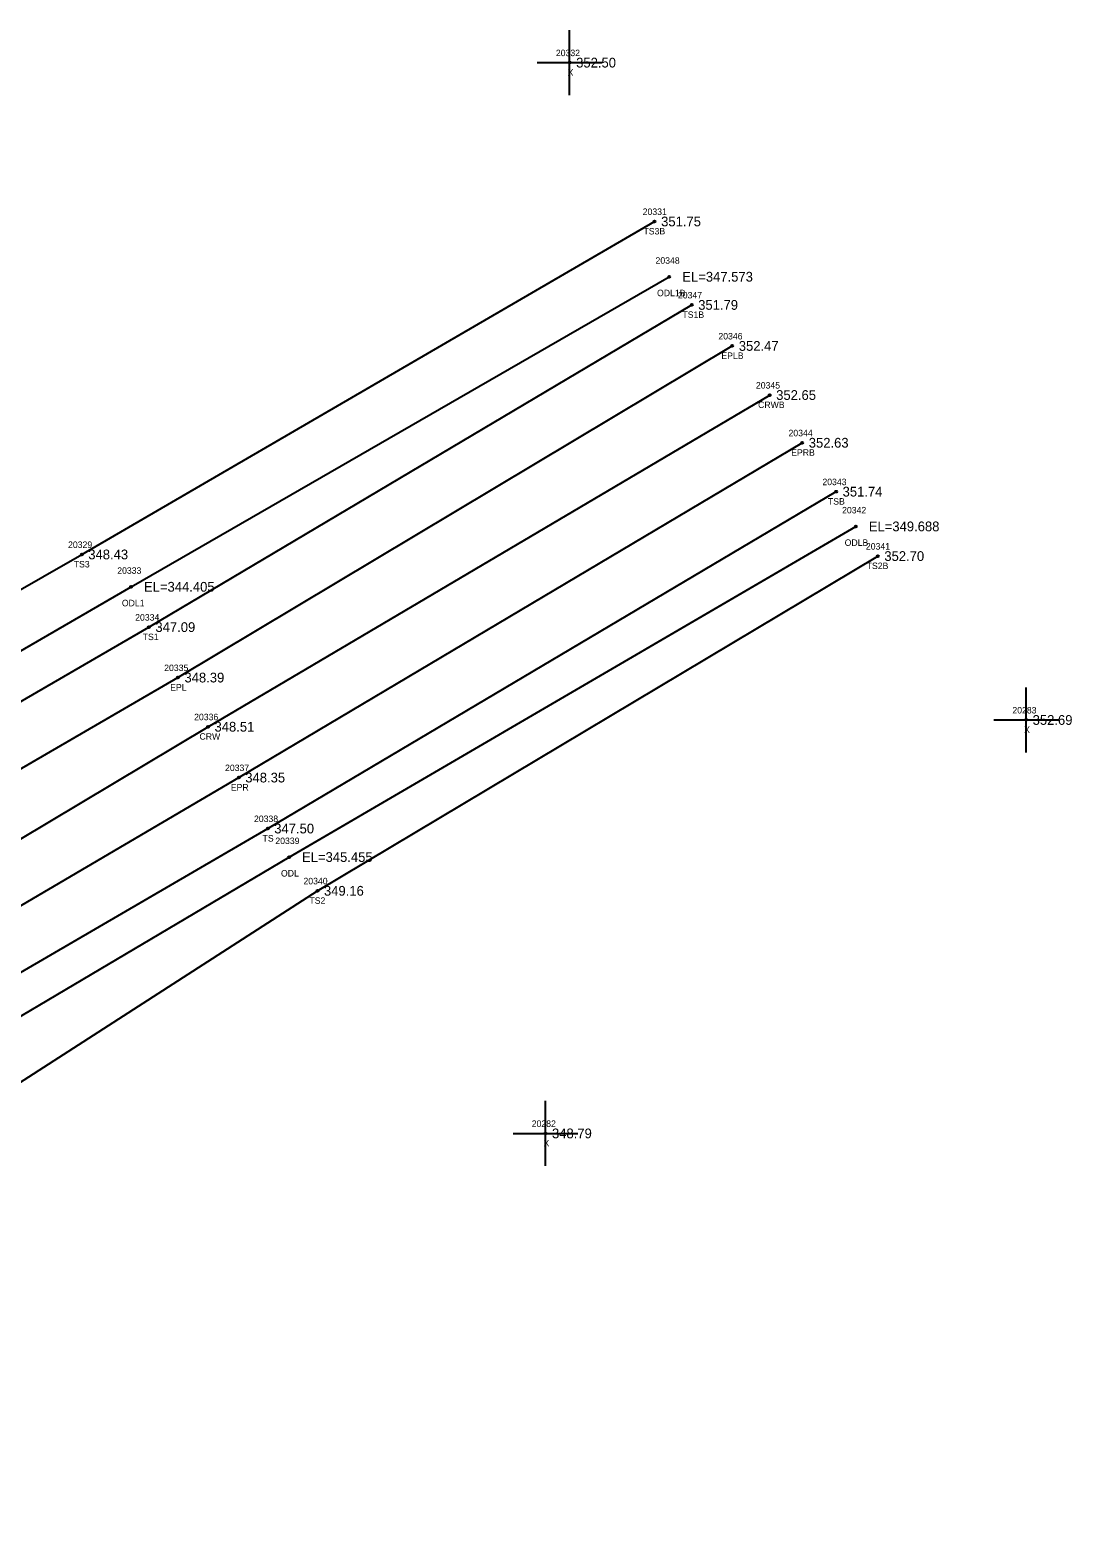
# Model space of a CAD drawing. Extents: x 2231109 to 2232328, y 1035718 to 1036919.
# Drawn here: x 2232167.8 to 2232328.2, y 1036686.7 to 1036918.9 of the extents above; entities that cross this region are included whole.
import ezdxf

# ---------------------------------------------------------------- set-up
doc = ezdxf.new("R2010")
doc.units = 0
for name, color, linetype in [('RD_DTM_BkLn1', 7, 'Continuous'), ('RD_DTM_BkLn2', 7, 'Continuous'), ('RD_DTM_BkLn_txCode', 7, 'Continuous'), ('RD_EX_H2O', 7, 'Continuous'), ('RD_EX_H2O_txCode', 7, 'Continuous'), ('RD_EX_Misc', 7, 'Continuous'), ('RD_EX_Misc_txCode', 7, 'Continuous'), ('RD_EX_Road', 7, 'Continuous'), ('RD_EX_Road_txCode', 7, 'Continuous'), ('RD_EX_TX_H2O_ELEV', 7, 'Continuous'), ('RD_EX_TX_Misc_ELEV', 7, 'Continuous'), ('RD_EX_TX_Road_ELEV', 7, 'Continuous'), ('RD_HC_Survey_ELEV', 7, 'Continuous'), ('RD_HC_Survey_txCode', 7, 'Continuous'), ('RD_SMD_Locator', 7, 'Continuous')]:
    doc.layers.add(name, color=color, linetype=linetype)

msp = doc.modelspace()

# ---------------------------------------------------------------- linework, layer by layer
at = {"layer": 'RD_DTM_BkLn1'}
msp.add_lwpolyline([(2231606.1, 1036462.92), (2231686.87, 1036511.89), (2231772.7, 1036562.84), (2231856.39, 1036612), (2231941.22, 1036662.52), (2232026.21, 1036712.41), (2232112.3, 1036762.07), (2232195.17, 1036811.63), (2232281.68, 1036862.71)], dxfattribs=at)
at = {"layer": 'RD_DTM_BkLn2'}
for points in [[(2231735.08, 1036566.99), (2231733.44, 1036571.38), (2231838.97, 1036638.65), (2231923.32, 1036688.26), (2232007.46, 1036737.64), (2232093.05, 1036790.84), (2232175.73, 1036838.16), (2232263.96, 1036889.44)], [(2231735.08, 1036566.99), (2231739.37, 1036565.02), (2231846.03, 1036627.82), (2231929.8, 1036677.63), (2232016.53, 1036728.58), (2232102.07, 1036778.24), (2232186.07, 1036826.97), (2232269.67, 1036876.59)], [(2231718.4, 1036498.96), (2231713.38, 1036506.48), (2231734.88, 1036516.5), (2231783.19, 1036543.78), (2231867.56, 1036594.75), (2232035.39, 1036697.6), (2232204.37, 1036795.95), (2232291.91, 1036847.83)], [(2231718.4, 1036498.96), (2231722.77, 1036493.83), (2231728.85, 1036494.16), (2231749.87, 1036507.43), (2231788.02, 1036534.9), (2231874.52, 1036587.15), (2231959.93, 1036637.18), (2232042.1, 1036685.84), (2232133.02, 1036735.49), (2232212.03, 1036786.36), (2232298.34, 1036837.91)]]:
    msp.add_lwpolyline(points, dxfattribs=at)
at = {"layer": 'RD_EX_H2O'}
for points in [[(2231741.7, 1036569.83), (2231843.08, 1036632.45), (2231926.34, 1036681.31), (2232011.09, 1036733.11), (2232099.56, 1036784.62), (2232183.31, 1036833.18), (2232266.22, 1036880.93)], [(2231720.77, 1036499.78), (2231736.43, 1036508.96), (2231742.17, 1036508.27), (2231745.29, 1036514.03), (2231785.52, 1036539.9), (2231869.59, 1036591.16), (2232038.46, 1036693), (2232129.43, 1036745.26), (2232207.65, 1036791.56), (2232294.95, 1036842.48)]]:
    msp.add_lwpolyline(points, dxfattribs=at)
at = {"layer": 'RD_EX_Misc'}
for p, q in [((2232250.87, 1036908.9), (2232250.87, 1036918.9)), ((2232245.87, 1036913.9), (2232255.87, 1036913.9)), ((2232321.18, 1036807.67), (2232321.18, 1036817.67)), ((2232316.18, 1036812.67), (2232326.18, 1036812.67)), ((2232247.15, 1036744), (2232247.15, 1036754)), ((2232242.15, 1036749), (2232252.15, 1036749))]:
    msp.add_line(p, q, dxfattribs=at)
at = {"layer": 'RD_EX_Road'}
for points in [[(2231606.1, 1036462.92), (2231601.27, 1036470.82), (2231681.58, 1036519.84), (2231764.99, 1036568.78), (2231851.5, 1036619.95), (2231935.62, 1036669.65), (2232021.78, 1036720.22), (2232106.75, 1036770.57), (2232190.54, 1036819.2), (2232275.92, 1036870.27)], [(2231606.1, 1036462.92), (2231610.57, 1036455.36), (2231692.09, 1036503.24), (2231706.07, 1036512.59), (2231777.1, 1036553.27), (2231861.39, 1036604.65), (2231946.39, 1036654.77), (2232031.07, 1036704.2), (2232117.06, 1036755.16), (2232199.91, 1036803.8), (2232286.7, 1036855.36)]]:
    msp.add_lwpolyline(points, dxfattribs=at)
at = {"layer": 'RD_SMD_Locator'}
for centre in [(2232250.87, 1036913.9), (2232263.96, 1036889.44), (2232266.22, 1036880.93), (2232269.67, 1036876.59), (2232275.92, 1036870.27), (2232281.68, 1036862.71), (2232286.7, 1036855.36), (2232291.91, 1036847.83), (2232294.95, 1036842.48), (2232175.73, 1036838.16), (2232298.34, 1036837.91), (2232183.31, 1036833.18), (2232186.07, 1036826.97), (2232190.54, 1036819.2), (2232195.17, 1036811.63), (2232321.18, 1036812.67), (2232199.91, 1036803.8), (2232204.37, 1036795.95), (2232207.65, 1036791.56), (2232212.03, 1036786.36), (2232247.15, 1036749)]:
    msp.add_circle(centre, 0.15, dxfattribs=at)

# ---------------------------------------------------------------- texts
at = {"layer": 'RD_DTM_BkLn_txCode'}
for s, p in [('20331', (2232262.12, 1036890.44)), ('TS3B', (2232262.24, 1036887.44)), ('20347', (2232267.55, 1036877.59)), ('TS1B', (2232268.24, 1036874.59)), ('20343', (2232289.8, 1036848.83)), ('TSB', (2232290.65, 1036845.83)), ('20329', (2232173.61, 1036839.16)), ('20341', (2232296.5, 1036838.91)), ('TS3', (2232174.49, 1036836.16)), ('TS2B', (2232296.62, 1036835.91)), ('20334', (2232183.95, 1036827.97)), ('TS1', (2232185.11, 1036824.97)), ('20338', (2232202.25, 1036796.95)), ('TS', (2232203.57, 1036793.95)), ('20340', (2232209.87, 1036787.36)), ('TS2', (2232210.79, 1036784.36))]:
    msp.add_text(s, height=1, dxfattribs=at).set_placement(p)
at = {"layer": 'RD_EX_H2O_txCode'}
for s, p in [('20348', (2232264.1, 1036882.93)), ('ODL1B', (2232264.33, 1036877.93)), ('20342', (2232292.83, 1036844.48)), ('ODLB', (2232293.23, 1036839.48)), ('20333', (2232181.19, 1036835.18)), ('ODL1', (2232181.9, 1036830.18)), ('20339', (2232205.54, 1036793.56)), ('ODL', (2232206.41, 1036788.56))]:
    msp.add_text(s, height=1, dxfattribs=at).set_placement(p)
at = {"layer": 'RD_EX_Misc_txCode'}
for s, p in [('20332', (2232248.75, 1036914.9)), ('X', (2232250.55, 1036911.9)), ('20283', (2232319.06, 1036813.67)), ('X', (2232320.87, 1036810.67)), ('20282', (2232245.03, 1036750)), ('X', (2232246.84, 1036747))]:
    msp.add_text(s, height=1, dxfattribs=at).set_placement(p)
at = {"layer": 'RD_EX_Road_txCode'}
for s, p in [('20346', (2232273.78, 1036871.27)), ('EPLB', (2232274.24, 1036868.27)), ('20344', (2232284.58, 1036856.36)), ('EPRB', (2232284.99, 1036853.36)), ('20335', (2232188.42, 1036820.2)), ('EPL', (2232189.34, 1036817.2)), ('20337', (2232197.79, 1036804.8)), ('EPR', (2232198.68, 1036801.8))]:
    msp.add_text(s, height=1, dxfattribs=at).set_placement(p)
at = {"layer": 'RD_EX_TX_H2O_ELEV'}
for s, p in [('EL=347.573', (2232268.22, 1036880.18)), ('EL=349.688', (2232296.95, 1036841.73)), ('EL=344.405', (2232185.31, 1036832.43)), ('EL=345.455', (2232209.65, 1036790.81))]:
    msp.add_text(s, height=1.5, dxfattribs=at).set_placement(p)
at = {"layer": 'RD_EX_TX_Misc_ELEV'}
for s, p in [('352.50', (2232251.87, 1036913.15)), ('351.75', (2232264.96, 1036888.69)), ('351.79', (2232270.67, 1036875.84)), ('351.74', (2232292.91, 1036847.08)), ('348.43', (2232176.73, 1036837.41)), ('352.70', (2232299.34, 1036837.16)), ('347.09', (2232187.07, 1036826.22)), ('352.69', (2232322.18, 1036811.92)), ('347.50', (2232205.37, 1036795.2)), ('349.16', (2232213.03, 1036785.61)), ('348.79', (2232248.15, 1036748.25))]:
    msp.add_text(s, height=1.5, dxfattribs=at).set_placement(p)
at = {"layer": 'RD_EX_TX_Road_ELEV'}
for s, p in [('352.47', (2232276.92, 1036869.52)), ('352.63', (2232287.7, 1036854.61)), ('348.39', (2232191.54, 1036818.45)), ('348.35', (2232200.91, 1036803.05))]:
    msp.add_text(s, height=1.5, dxfattribs=at).set_placement(p)
at = {"layer": 'RD_HC_Survey_ELEV'}
for s, p in [('352.65', (2232282.68, 1036861.96)), ('348.51', (2232196.17, 1036810.88))]:
    msp.add_text(s, height=1.5, dxfattribs=at).set_placement(p)
at = {"layer": 'RD_HC_Survey_txCode'}
for s, p in [('20345', (2232279.56, 1036863.71)), ('CRWB', (2232279.89, 1036860.71)), ('20336', (2232193.03, 1036812.63)), ('CRW', (2232193.86, 1036809.63))]:
    msp.add_text(s, height=1, dxfattribs=at).set_placement(p)

doc.saveas('drawing.dxf')
